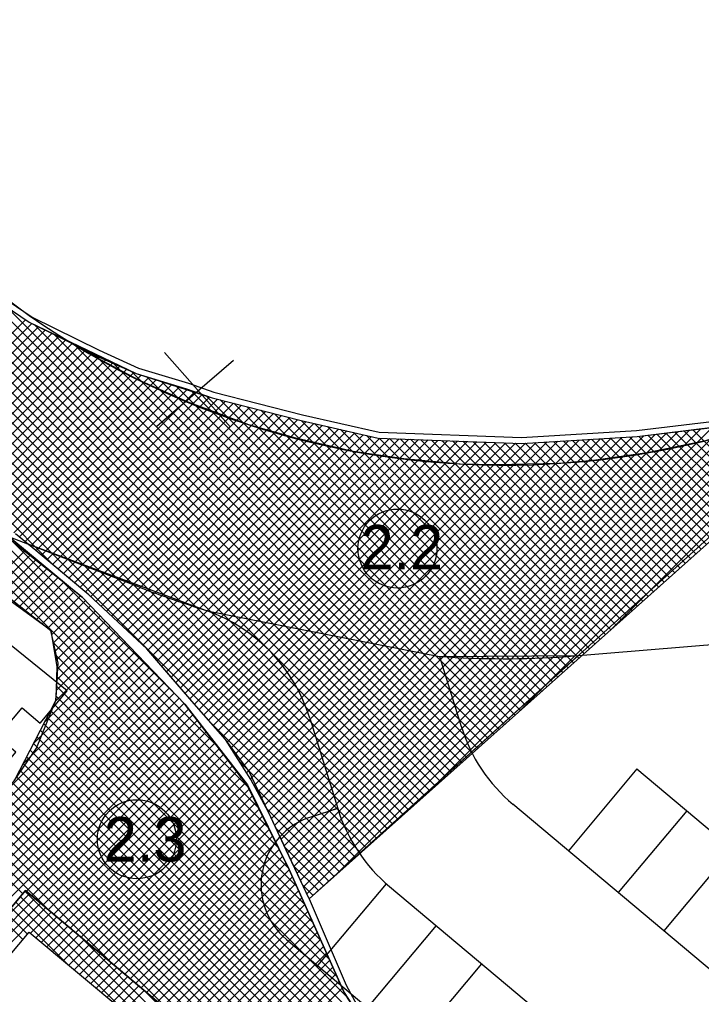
# Model space of a CAD drawing. Extents: x -438410 to -437811, y -1133174 to -1132817.
# Drawn here: x -438131.22 to -438102.46, y -1132971.41 to -1132930.32 of the extents above; entities that cross this region are included whole.
import ezdxf

# ---------------------------------------------------------------- set-up
doc = ezdxf.new("R2010")
doc.units = 0
for name, color, linetype in [('10 - legenda', 7, 'Continuous'), ('Vrstva 1', 7, 'Continuous'), ('Vrstva 5', 7, 'Continuous')]:
    doc.layers.add(name, color=color, linetype=linetype)

msp = doc.modelspace()

# ---------------------------------------------------------------- linework, layer by layer
at = {"layer": '10 - legenda'}
for p, q in [((-438148.495, -1132927.399), (-438113.459, -1132962.435)), ((-438148.574, -1132927.744), (-438113.683, -1132962.635)), ((-438148.653, -1132928.089), (-438113.907, -1132962.835)), ((-438148.812, -1132928.779), (-438114.356, -1132963.235)), ((-438148.733, -1132928.434), (-438114.132, -1132963.035)), ((-438148.891, -1132929.124), (-438114.58, -1132963.435)), ((-438148.971, -1132929.469), (-438114.805, -1132963.635)), ((-438149.05, -1132929.814), (-438115.029, -1132963.835)), ((-438149.129, -1132930.159), (-438115.253, -1132964.035)), ((-438149.288, -1132930.848), (-438115.702, -1132964.435)), ((-438149.209, -1132930.503), (-438115.478, -1132964.235)), ((-438149.368, -1132931.193), (-438115.926, -1132964.634)), ((-438149.447, -1132931.538), (-438116.151, -1132964.834)), ((-438149.526, -1132931.883), (-438116.375, -1132965.034)), ((-438149.606, -1132932.228), (-438116.599, -1132965.234)), ((-438149.764, -1132932.918), (-438117.048, -1132965.634)), ((-438149.685, -1132932.573), (-438116.824, -1132965.434)), ((-438149.844, -1132933.263), (-438129.751, -1132953.356)), ((-438136.551, -1132938.919), (-438113.234, -1132962.235)), ((-438134.389, -1132940.656), (-438113.01, -1132962.035)), ((-438133.074, -1132941.547), (-438112.786, -1132961.835)), ((-438131.759, -1132942.437), (-438112.561, -1132961.636)), ((-438136.978, -1132948.977), (-438130.972, -1132942.971)), ((-438136.694, -1132949.117), (-438130.707, -1132943.13)), ((-438130.584, -1132943.188), (-438112.337, -1132961.436)), ((-438136.41, -1132949.257), (-438130.42, -1132943.267)), ((-438136.126, -1132949.397), (-438130.133, -1132943.404)), ((-438135.842, -1132949.538), (-438129.846, -1132943.542)), ((-438129.77, -1132943.579), (-438112.113, -1132961.236)), ((-438135.558, -1132949.678), (-438129.56, -1132943.679)), ((-438135.274, -1132949.818), (-438129.273, -1132943.817)), ((-438134.99, -1132949.958), (-438128.986, -1132943.954)), ((-438128.955, -1132943.969), (-438111.888, -1132961.036)), ((-438134.706, -1132950.099), (-438128.699, -1132944.092)), ((-438134.422, -1132950.239), (-438128.412, -1132944.229)), ((-438134.145, -1132950.386), (-438128.126, -1132944.366)), ((-438128.141, -1132944.359), (-438111.664, -1132960.836)), ((-438125.108, -1132944.351), (-438122.329, -1132947.502)), ((-438133.876, -1132950.542), (-438127.839, -1132944.504)), ((-438133.608, -1132950.698), (-438127.552, -1132944.641)), ((-438133.34, -1132950.854), (-438127.265, -1132944.779)), ((-438127.326, -1132944.749), (-438111.44, -1132960.636)), ((-438125.436, -1132947.457), (-438122.194, -1132944.677)), ((-438133.072, -1132951.01), (-438126.978, -1132944.916)), ((-438132.804, -1132951.166), (-438126.691, -1132945.054)), ((-438132.536, -1132951.322), (-438126.405, -1132945.191)), ((-438126.512, -1132945.14), (-438111.215, -1132960.436)), ((-438132.268, -1132951.478), (-438126.096, -1132945.306)), ((-438131.999, -1132951.634), (-438125.774, -1132945.409)), ((-438131.731, -1132951.791), (-438125.452, -1132945.511)), ((-438131.463, -1132951.947), (-438125.13, -1132945.614)), ((-438125.839, -1132945.388), (-438110.991, -1132960.236)), ((-438125.217, -1132945.586), (-438110.767, -1132960.036)), ((-438131.222, -1132952.129), (-438124.808, -1132945.716)), ((-438130.99, -1132952.322), (-438124.486, -1132945.818)), ((-438130.759, -1132952.515), (-438124.164, -1132945.921)), ((-438130.527, -1132952.708), (-438123.843, -1132946.023)), ((-438124.595, -1132945.784), (-438110.542, -1132959.836)), ((-438123.972, -1132945.982), (-438110.318, -1132959.636)), ((-438130.296, -1132952.901), (-438123.521, -1132946.126)), ((-438130.065, -1132953.094), (-438123.199, -1132946.228)), ((-438129.833, -1132953.287), (-438122.866, -1132946.32)), ((-438129.602, -1132953.48), (-438122.529, -1132946.407)), ((-438123.35, -1132946.18), (-438110.094, -1132959.436)), ((-438122.758, -1132946.348), (-438109.869, -1132959.236)), ((-438129.371, -1132953.673), (-438122.192, -1132946.494)), ((-438129.139, -1132953.865), (-438121.854, -1132946.58)), ((-438128.908, -1132954.058), (-438121.517, -1132946.667)), ((-438128.677, -1132954.251), (-438121.179, -1132946.754)), ((-438128.445, -1132954.444), (-438120.842, -1132946.841)), ((-438122.187, -1132946.495), (-438109.645, -1132959.037)), ((-438121.615, -1132946.642), (-438109.421, -1132958.837)), ((-438121.044, -1132946.789), (-438109.196, -1132958.637)), ((-438128.218, -1132954.641), (-438120.504, -1132946.928)), ((-438127.999, -1132954.846), (-438120.167, -1132947.014)), ((-438127.779, -1132955.051), (-438119.83, -1132947.101)), ((-438127.56, -1132955.256), (-438119.492, -1132947.188)), ((-438127.341, -1132955.461), (-438119.15, -1132947.27)), ((-438120.473, -1132946.936), (-438108.972, -1132958.437)), ((-438119.902, -1132947.083), (-438108.748, -1132958.237)), ((-438119.377, -1132966.589), (-438100.071, -1132947.284)), ((-438119.331, -1132947.229), (-438108.523, -1132958.037)), ((-438119.241, -1132966.877), (-438099.589, -1132947.226)), ((-438119.105, -1132967.166), (-438099.107, -1132947.168)), ((-438117.976, -1132966.461), (-438098.625, -1132947.11)), ((-438114.077, -1132962.987), (-438098.143, -1132947.052)), ((-438110.179, -1132959.512), (-438097.661, -1132946.994)), ((-438106.28, -1132956.038), (-438097.179, -1132946.936)), ((-438127.121, -1132955.666), (-438118.804, -1132947.348)), ((-438126.902, -1132955.871), (-438118.458, -1132947.426)), ((-438126.683, -1132956.076), (-438118.111, -1132947.505)), ((-438126.463, -1132956.281), (-438117.765, -1132947.583)), ((-438126.244, -1132956.486), (-438117.419, -1132947.661)), ((-438120.327, -1132964.569), (-438103.446, -1132947.689)), ((-438120.191, -1132964.858), (-438102.964, -1132947.631)), ((-438120.055, -1132965.146), (-438102.482, -1132947.573)), ((-438119.92, -1132965.435), (-438102, -1132947.515)), ((-438119.784, -1132965.723), (-438101.518, -1132947.457)), ((-438119.648, -1132966.012), (-438101.036, -1132947.399)), ((-438119.512, -1132966.3), (-438100.554, -1132947.342)), ((-438118.783, -1132947.353), (-438108.299, -1132957.837)), ((-438118.235, -1132947.477), (-438108.075, -1132957.637)), ((-438117.687, -1132947.601), (-438107.85, -1132957.437)), ((-438103.582, -1132947.705), (-438100.447, -1132950.84)), ((-438103.203, -1132947.66), (-438100.223, -1132950.64)), ((-438102.824, -1132947.614), (-438099.998, -1132950.44)), ((-438126.025, -1132956.691), (-438117.073, -1132947.739)), ((-438125.81, -1132956.9), (-438116.727, -1132947.817)), ((-438125.613, -1132957.127), (-438116.381, -1132947.896)), ((-438125.416, -1132957.354), (-438116.026, -1132947.964)), ((-438125.218, -1132957.581), (-438115.617, -1132947.98)), ((-438125.021, -1132957.808), (-438115.208, -1132947.995)), ((-438124.824, -1132958.035), (-438114.799, -1132948.01)), ((-438124.626, -1132958.262), (-438114.39, -1132948.026)), ((-438124.429, -1132958.489), (-438113.981, -1132948.041)), ((-438124.232, -1132958.716), (-438113.572, -1132948.056)), ((-438124.035, -1132958.943), (-438113.163, -1132948.071)), ((-438123.837, -1132959.17), (-438112.754, -1132948.087)), ((-438123.64, -1132959.397), (-438112.345, -1132948.102)), ((-438123.443, -1132959.624), (-438111.936, -1132948.117)), ((-438121.974, -1132961.549), (-438108.522, -1132948.097)), ((-438121.808, -1132961.808), (-438108.07, -1132948.07)), ((-438121.643, -1132962.067), (-438107.619, -1132948.043)), ((-438121.478, -1132962.326), (-438107.168, -1132948.016)), ((-438121.328, -1132962.6), (-438106.716, -1132947.989)), ((-438121.18, -1132962.876), (-438106.265, -1132947.962)), ((-438121.031, -1132963.152), (-438105.813, -1132947.935)), ((-438120.883, -1132963.428), (-438105.362, -1132947.907)), ((-438120.735, -1132963.704), (-438104.893, -1132947.862)), ((-438120.598, -1132963.992), (-438104.411, -1132947.805)), ((-438120.463, -1132964.281), (-438103.929, -1132947.747)), ((-438117.139, -1132947.724), (-438107.626, -1132957.237)), ((-438116.591, -1132947.848), (-438107.402, -1132957.037)), ((-438116.051, -1132947.963), (-438107.177, -1132956.837)), ((-438115.61, -1132947.98), (-438106.953, -1132956.637)), ((-438115.17, -1132947.996), (-438106.729, -1132956.438)), ((-438114.729, -1132948.013), (-438106.504, -1132956.238)), ((-438114.288, -1132948.029), (-438106.28, -1132956.038)), ((-438113.847, -1132948.046), (-438106.056, -1132955.838)), ((-438113.407, -1132948.062), (-438105.831, -1132955.638)), ((-438112.966, -1132948.079), (-438105.607, -1132955.438)), ((-438112.525, -1132948.095), (-438105.382, -1132955.238)), ((-438112.084, -1132948.112), (-438105.158, -1132955.038)), ((-438108.695, -1132948.107), (-438103.363, -1132953.439)), ((-438108.294, -1132948.083), (-438103.139, -1132953.239)), ((-438107.894, -1132948.059), (-438102.915, -1132953.039)), ((-438107.494, -1132948.035), (-438102.69, -1132952.839)), ((-438107.094, -1132948.011), (-438102.466, -1132952.639)), ((-438106.693, -1132947.987), (-438102.242, -1132952.439)), ((-438106.293, -1132947.963), (-438102.017, -1132952.239)), ((-438105.893, -1132947.939), (-438101.793, -1132952.039)), ((-438105.493, -1132947.915), (-438101.569, -1132951.839)), ((-438105.097, -1132947.887), (-438101.344, -1132951.639)), ((-438104.718, -1132947.841), (-438101.12, -1132951.439)), ((-438104.339, -1132947.796), (-438100.896, -1132951.239)), ((-438103.96, -1132947.75), (-438100.671, -1132951.04)), ((-438123.245, -1132959.851), (-438111.527, -1132948.133)), ((-438123.048, -1132960.078), (-438111.118, -1132948.148)), ((-438122.851, -1132960.305), (-438110.709, -1132948.163)), ((-438122.653, -1132960.532), (-438110.3, -1132948.179)), ((-438122.47, -1132960.772), (-438109.876, -1132948.178)), ((-438122.304, -1132961.031), (-438109.424, -1132948.151)), ((-438122.139, -1132961.29), (-438108.973, -1132948.124)), ((-438111.644, -1132948.128), (-438104.934, -1132954.838)), ((-438111.203, -1132948.145), (-438104.709, -1132954.638)), ((-438110.762, -1132948.161), (-438104.485, -1132954.438)), ((-438110.321, -1132948.178), (-438104.261, -1132954.238)), ((-438109.895, -1132948.18), (-438104.036, -1132954.038)), ((-438109.495, -1132948.156), (-438103.812, -1132953.838)), ((-438109.095, -1132948.131), (-438103.588, -1132953.639)), ((-438134.594, -1132950.937), (-438120.304, -1132965.228)), ((-438134.449, -1132950.659), (-438120.721, -1132964.387)), ((-438133.795, -1132950.888), (-438121.138, -1132963.545)), ((-438134.74, -1132951.216), (-438119.886, -1132966.07)), ((-438132.681, -1132951.578), (-438121.555, -1132962.704)), ((-438131.471, -1132952.364), (-438122.863, -1132960.971)), ((-438132.397, -1132954.104), (-438131.017, -1132952.724)), ((-438132.16, -1132954.291), (-438130.781, -1132952.912)), ((-438131.923, -1132954.479), (-438130.544, -1132953.1)), ((-438131.686, -1132954.666), (-438130.308, -1132953.288)), ((-438131.449, -1132954.853), (-438130.072, -1132953.476)), ((-438131.212, -1132955.041), (-438129.835, -1132953.664)), ((-438130.975, -1132955.228), (-438129.599, -1132953.852)), ((-438130.738, -1132955.415), (-438129.362, -1132954.04)), ((-438130.501, -1132955.603), (-438129.126, -1132954.227)), ((-438129.403, -1132954.007), (-438124.702, -1132958.709)), ((-438130.264, -1132955.79), (-438128.89, -1132954.415)), ((-438130.027, -1132955.977), (-438128.653, -1132954.603)), ((-438129.875, -1132956.249), (-438128.437, -1132954.811)), ((-438129.813, -1132956.611), (-438128.229, -1132955.028)), ((-438129.751, -1132956.974), (-438128.022, -1132955.244)), ((-438129.689, -1132957.336), (-438127.814, -1132955.461)), ((-438129.662, -1132958.157), (-438127.399, -1132955.894)), ((-438129.647, -1132957.718), (-438127.607, -1132955.678)), ((-438129.719, -1132959.063), (-438126.984, -1132956.328)), ((-438129.676, -1132958.596), (-438127.191, -1132956.111)), ((-438130.171, -1132959.939), (-438126.776, -1132956.544)), ((-438129.822, -1132956.558), (-438119.536, -1132966.844)), ((-438131.074, -1132961.691), (-438126.361, -1132956.978)), ((-438130.623, -1132960.815), (-438126.568, -1132956.761)), ((-438129.735, -1132957.07), (-438119.192, -1132967.613)), ((-438140.401, -1132971.442), (-438126.153, -1132957.194)), ((-438140.306, -1132971.772), (-438125.946, -1132957.411)), ((-438140.212, -1132972.101), (-438125.738, -1132957.627)), ((-438140.117, -1132972.431), (-438125.53, -1132957.844)), ((-438129.647, -1132957.582), (-438118.848, -1132968.381)), ((-438140.022, -1132972.76), (-438125.323, -1132958.061)), ((-438139.928, -1132973.09), (-438125.115, -1132958.277)), ((-438129.656, -1132957.997), (-438118.504, -1132969.149)), ((-438139.833, -1132973.419), (-438124.907, -1132958.494)), ((-438139.736, -1132973.747), (-438124.7, -1132958.711)), ((-438129.67, -1132958.407), (-438118.16, -1132969.917)), ((-438139.501, -1132973.936), (-438124.492, -1132958.927)), ((-438139.265, -1132974.125), (-438124.285, -1132959.144)), ((-438129.768, -1132959.158), (-438117.404, -1132971.522)), ((-438129.684, -1132958.818), (-438117.816, -1132970.685)), ((-438139.03, -1132974.314), (-438124.096, -1132959.379)), ((-438138.795, -1132974.503), (-438123.911, -1132959.618)), ((-438129.912, -1132959.438), (-438116.639, -1132972.712)), ((-438130.928, -1132967.061), (-438123.725, -1132959.858)), ((-438130.201, -1132959.998), (-438081.765, -1133008.433)), ((-438130.057, -1132959.718), (-438114.95, -1132974.824)), ((-438123.178, -1132959.928), (-438117.272, -1132965.834)), ((-438130.698, -1132967.255), (-438123.54, -1132960.097)), ((-438130.468, -1132967.448), (-438123.355, -1132960.336)), ((-438130.345, -1132960.277), (-438081.816, -1133008.807)), ((-438130.634, -1132960.837), (-438102.656, -1132988.816)), ((-438130.49, -1132960.557), (-438081.866, -1133009.181)), ((-438130.237, -1132967.642), (-438123.17, -1132960.575)), ((-438130.007, -1132967.836), (-438122.985, -1132960.814)), ((-438130.778, -1132961.117), (-438105.237, -1132986.659)), ((-438129.777, -1132968.03), (-438122.8, -1132961.053)), ((-438131.067, -1132961.677), (-438109.295, -1132983.449)), ((-438130.923, -1132961.397), (-438107.818, -1132984.502)), ((-438129.546, -1132968.224), (-438122.615, -1132961.292)), ((-438129.316, -1132968.418), (-438122.43, -1132961.532)), ((-438121.96, -1132961.571), (-438117.497, -1132966.034)), ((-438131.211, -1132961.957), (-438109.488, -1132983.68)), ((-438129.085, -1132968.612), (-438122.244, -1132961.771)), ((-438128.855, -1132968.806), (-438122.059, -1132962.01)), ((-438131.539, -1132962.478), (-438109.874, -1132984.143)), ((-438131.356, -1132962.237), (-438109.681, -1132983.912)), ((-438128.625, -1132968.999), (-438121.874, -1132962.249)), ((-438128.394, -1132969.193), (-438121.689, -1132962.488)), ((-438132.015, -1132962.85), (-438110.26, -1132984.605)), ((-438131.777, -1132962.664), (-438110.067, -1132984.374)), ((-438128.164, -1132969.387), (-438121.53, -1132962.754)), ((-438121.297, -1132962.658), (-438117.721, -1132966.234)), ((-438132.492, -1132963.222), (-438110.646, -1132985.068)), ((-438132.254, -1132963.036), (-438110.453, -1132984.837)), ((-438127.934, -1132969.581), (-438121.39, -1132963.037)), ((-438127.703, -1132969.775), (-438121.249, -1132963.321)), ((-438132.969, -1132963.594), (-438112.542, -1132984.021)), ((-438132.73, -1132963.408), (-438110.839, -1132985.299)), ((-438127.473, -1132969.969), (-438121.109, -1132963.605)), ((-438120.805, -1132963.575), (-438117.945, -1132966.434)), ((-438133.445, -1132963.966), (-438127.28, -1132970.131)), ((-438133.207, -1132963.78), (-438124.602, -1132972.384)), ((-438127.242, -1132970.163), (-438120.968, -1132963.888)), ((-438133.922, -1132964.338), (-438131.086, -1132967.174)), ((-438133.683, -1132964.152), (-438129.958, -1132967.878)), ((-438127.012, -1132970.357), (-438120.827, -1132964.172)), ((-438126.782, -1132970.551), (-438120.687, -1132964.456)), ((-438120.409, -1132964.394), (-438118.17, -1132966.634)), ((-438126.551, -1132970.744), (-438120.546, -1132964.739)), ((-438126.321, -1132970.938), (-438120.405, -1132965.023)), ((-438126.09, -1132971.132), (-438120.265, -1132965.306)), ((-438120.032, -1132965.196), (-438118.394, -1132966.834)), ((-438125.86, -1132971.326), (-438120.124, -1132965.59)), ((-438125.63, -1132971.52), (-438119.983, -1132965.874)), ((-438125.399, -1132971.714), (-438119.843, -1132966.158)), ((-438119.655, -1132965.997), (-438118.618, -1132967.034)), ((-438125.169, -1132971.908), (-438119.712, -1132966.451)), ((-438124.939, -1132972.102), (-438119.581, -1132966.744)), ((-438119.278, -1132966.798), (-438118.843, -1132967.233)), ((-438134.718, -1132971.506), (-438130.572, -1132967.36)), ((-438132.515, -1132968.879), (-438130.803, -1132967.166)), ((-438131.185, -1132967.293), (-438124.098, -1132974.38)), ((-438130.992, -1132967.062), (-438122.652, -1132975.401)), ((-438124.708, -1132972.295), (-438119.45, -1132967.037)), ((-438124.478, -1132972.489), (-438119.318, -1132967.33)), ((-438137.727, -1132975.364), (-438130.112, -1132967.748)), ((-438136.921, -1132974.133), (-438130.342, -1132967.554)), ((-438131.572, -1132967.754), (-438129.213, -1132970.113)), ((-438131.379, -1132967.523), (-438126.655, -1132972.247)), ((-438124.247, -1132972.683), (-438119.187, -1132967.623)), ((-438131.959, -1132968.216), (-438131.081, -1132969.094)), ((-438131.766, -1132967.985), (-438130.887, -1132968.863)), ((-438130.761, -1132968.822), (-438129.881, -1132967.942)), ((-438130.53, -1132969.015), (-438129.651, -1132968.136)), ((-438124.017, -1132972.877), (-438119.056, -1132967.916)), ((-438123.787, -1132973.071), (-438118.925, -1132968.209)), ((-438130.298, -1132969.208), (-438129.421, -1132968.33)), ((-438130.067, -1132969.401), (-438129.19, -1132968.524)), ((-438123.556, -1132973.265), (-438118.794, -1132968.502)), ((-438129.836, -1132969.594), (-438128.96, -1132968.718)), ((-438129.605, -1132969.787), (-438128.729, -1132968.911)), ((-438128.656, -1132968.973), (-438122.459, -1132975.17)), ((-438123.326, -1132973.459), (-438118.662, -1132968.795)), ((-438129.373, -1132969.979), (-438128.499, -1132969.105)), ((-438129.142, -1132970.172), (-438128.269, -1132969.299)), ((-438123.095, -1132973.653), (-438118.531, -1132969.088)), ((-438122.865, -1132973.846), (-438118.4, -1132969.381)), ((-438128.911, -1132970.365), (-438128.038, -1132969.493)), ((-438128.679, -1132970.558), (-438127.808, -1132969.687)), ((-438128.448, -1132970.751), (-438127.577, -1132969.881)), ((-438122.635, -1132974.04), (-438118.269, -1132969.674)), ((-438128.217, -1132970.944), (-438127.347, -1132970.075)), ((-438127.985, -1132971.137), (-438127.117, -1132970.269)), ((-438122.404, -1132974.234), (-438118.138, -1132969.968)), ((-438122.174, -1132974.428), (-438118.006, -1132970.261)), ((-438127.754, -1132971.33), (-438126.886, -1132970.462)), ((-438127.523, -1132971.523), (-438126.656, -1132970.656)), ((-438122.298, -1132974.976), (-438117.875, -1132970.554)), ((-438127.291, -1132971.716), (-438126.426, -1132970.85)), ((-438127.06, -1132971.909), (-438126.195, -1132971.044)), ((-438122.56, -1132975.663), (-438117.744, -1132970.847)), ((-438126.829, -1132972.102), (-438125.965, -1132971.238)), ((-438125.978, -1132971.226), (-438122.266, -1132974.939)), ((-438122.329, -1132975.856), (-438117.613, -1132971.14))]:
    msp.add_line(p, q, dxfattribs=at)
for points in [[(-438146.983, -1132924.842), (-438144.552, -1132929.987), (-438143.081, -1132932.128), (-438139.741, -1132936.125), (-438135.173, -1132940.125), (-438130.812, -1132943.079), (-438127.97, -1132944.486), (-438126.298, -1132945.242), (-438124.176, -1132945.89), (-438123.093, -1132946.262), (-438119.349, -1132947.225), (-438116.088, -1132947.962), (-438110.041, -1132948.188), (-438105.174, -1132947.896), (-438095.894, -1132946.782)], [(-438146.757, -1132924.735), (-438144.335, -1132929.862), (-438142.882, -1132931.977), (-438139.562, -1132935.95), (-438135.02, -1132939.927), (-438130.686, -1132942.863), (-438127.863, -1132944.26), (-438126.21, -1132945.008), (-438124.099, -1132945.652), (-438123.021, -1132946.022), (-438119.29, -1132946.982), (-438116.055, -1132947.713), (-438110.044, -1132947.938), (-438105.196, -1132947.647), (-438095.924, -1132946.534)], [(-438062.981, -1132924.836), (-438065.997, -1132924.747), (-438069.426, -1132925.449), (-438073.105, -1132927.148), (-438074.983, -1132928.454), (-438095.924, -1132946.534), (-438119.005, -1132967.378), (-438117.439, -1132971.017), (-438116.805, -1132972.178), (-438115.711, -1132973.535), (-438114.422, -1132975.132), (-438106.298, -1132981.775), (-438086.742, -1132998.074)], [(-438135.173, -1132940.125), (-438130.812, -1132943.079), (-438126.298, -1132945.242), (-438123.093, -1132946.262), (-438119.349, -1132947.225), (-438116.088, -1132947.962), (-438110.041, -1132948.188), (-438105.174, -1132947.896), (-438095.894, -1132946.782), (-438119.005, -1132967.378), (-438119.971, -1132965.325), (-438120.725, -1132963.723), (-438121.46, -1132962.354), (-438122.54, -1132960.663), (-438123.851, -1132959.154), (-438125.855, -1132956.849), (-438128.297, -1132954.568), (-438130.381, -1132952.83), (-438131.389, -1132951.99)], [(-438155.418, -1132951.658), (-438154.459, -1132949.928), (-438152.986, -1132948.431), (-438150.952, -1132947.355), (-438149.044, -1132947.04), (-438145.423, -1132947.152), (-438140.626, -1132947.906), (-438137.256, -1132949.17), (-438134.381, -1132950.515), (-438131.551, -1132952.201), (-438128.583, -1132954.659), (-438124.25, -1132959.18), (-438121.599, -1132962.576), (-438119.849, -1132966.145), (-438117.528, -1132971.329), (-438116.418, -1132973.046), (-438114.656, -1132975.171), (-438090.957, -1132994.89), (-438086.882, -1132998.283), (-438085.153, -1132999.203), (-438076.272, -1133002.948), (-438073.404, -1133002.03)], [(-438116.314, -1132973.216), (-438117.528, -1132971.329), (-438119.849, -1132966.145), (-438121.614, -1132962.586), (-438124.25, -1132959.18), (-438128.583, -1132954.659), (-438131.681, -1132952.197)], [(-438132.442, -1132954.068), (-438129.905, -1132956.074), (-438129.643, -1132957.603), (-438129.69, -1132959.007), (-438131.441, -1132962.402)], [(-438137.86, -1132975.253), (-438130.965, -1132967.03), (-438121.978, -1132974.593)]]:
    msp.add_lwpolyline(points, dxfattribs=at)
for points in [[(-438128.593, -1132944.225), (-438126.298, -1132945.242), (-438123.093, -1132946.262), (-438119.349, -1132947.225), (-438116.088, -1132947.962), (-438110.041, -1132948.188), (-438105.174, -1132947.896), (-438099.472, -1132947.198), (-438102.289, -1132948.077), (-438104.748, -1132948.588), (-438107.008, -1132948.906), (-438108.474, -1132949.037), (-438111.123, -1132949.095), (-438112.638, -1132949.055), (-438115.01, -1132948.842), (-438117.148, -1132948.522), (-438119.569, -1132947.968), (-438121.555, -1132947.401), (-438124.112, -1132946.443), (-438126.196, -1132945.519), (-438127.743, -1132944.698)], [(-438153.362, -1132953.683), (-438141.329, -1132963.718), (-438139.289, -1132965.196), (-438137.396, -1132965.333), (-438135.25, -1132964.978), (-438134.136, -1132964.505), (-438132.444, -1132963.434), (-438131.441, -1132962.402), (-438130.504, -1132961.025), (-438129.696, -1132959.017), (-438129.592, -1132957.446), (-438129.905, -1132956.074), (-438133.603, -1132953.391), (-438137.63, -1132951.233), (-438141.796, -1132949.8), (-438144.368, -1132949.286), (-438146.02, -1132949.095), (-438148.81, -1132949.169), (-438151.016, -1132949.704), (-438152.461, -1132950.801), (-438153.127, -1132951.692), (-438153.435, -1132952.654), (-438153.553, -1132952.973)], [(-438130.878, -1132952.418), (-438123.306, -1132955.241), (-438113.511, -1132957.165), (-438107.659, -1132957.123), (-438119.005, -1132967.378), (-438120.725, -1132963.723), (-438121.529, -1132962.014), (-438122.54, -1132960.663), (-438123.851, -1132959.154), (-438124.84, -1132958.017), (-438125.855, -1132956.849), (-438128.297, -1132954.568)], [(-438136.916, -1132976.04), (-438130.815, -1132968.777), (-438122.743, -1132975.51), (-438121.978, -1132974.593), (-438130.965, -1132967.03), (-438137.86, -1132975.253)]]:
    msp.add_lwpolyline(points, close=True, dxfattribs=at)
for centre in [(-438115.283, -1132952.616), (-438126.269, -1132964.867)]:
    msp.add_circle(centre, 1.666, dxfattribs=at)
at = {"layer": 'Vrstva 1'}
for p, q in [((-438126.16, -1132954.25), (-438141.307, -1132948.405)), ((-438108.146, -1132957.17), (-438092.173, -1132955.846)), ((-438113.511, -1132957.165), (-438112.595, -1132960.119)), ((-438118.983, -1132959.758), (-438117.801, -1132963.571)), ((-438105.183, -1132961.903), (-438108.073, -1132965.352)), ((-438105.183, -1132961.903), (-438094.643, -1132970.733)), ((-438117.801, -1132963.571), (-438118.938, -1132963.931)), ((-438117.866, -1132963.592), (-438118.183, -1132963.691)), ((-438110.419, -1132963.379), (-438094.463, -1132976.746)), ((-438103.075, -1132963.669), (-438105.965, -1132967.118)), ((-438101.159, -1132965.274), (-438104.048, -1132968.724)), ((-438115.759, -1132966.741), (-438118.649, -1132970.19)), ((-438115.61, -1132966.865), (-438098.33, -1132981.342)), ((-438113.651, -1132968.507), (-438116.541, -1132971.956)), ((-438119.96, -1132969.091), (-438118.649, -1132970.19)), ((-438118.649, -1132970.19), (-438104.276, -1132982.231)), ((-438111.734, -1132970.112), (-438114.624, -1132973.562))]:
    msp.add_line(p, q, dxfattribs=at)
msp.add_lwpolyline([(-438132.181, -1132956.223), (-438136.968, -1132962.209), (-438134.136, -1132964.505), (-438131.375, -1132961.204), (-438132.148, -1132960.557), (-438131.114, -1132959.322), (-438130.348, -1132959.977), (-438129.211, -1132958.606)], close=True, dxfattribs=at)
for centre, radius, start, end in [((-438110.755, -1132914.104), 35, 232.5685, 308.9476), ((-438110.755, -1132914.104), 43, 249.0065, 253.0447), ((-438125.669, -1132961.83), 7, 17.2179, 70.2715), ((-438110.786, -1132917.258), 40, 266.0939, 273.7838), ((-438105.907, -1132958.035), 7, 197.2179, 230.0448), ((-438111.115, -1132961.499), 7, 197.2179, 230.0448), ((-438118.034, -1132966.791), 3, 107.5443, 230.0448)]:
    msp.add_arc(centre, radius, start, end, dxfattribs=at)

# ---------------------------------------------------------------- texts
at = {"layer": 'Vrstva 5'}
for s, p in [('2.2', (-438116.839, -1132953.498)), ('2.3', (-438127.669, -1132965.805))]:
    msp.add_text(s, height=1.875, dxfattribs=at).set_placement(p)

doc.saveas('drawing.dxf')
